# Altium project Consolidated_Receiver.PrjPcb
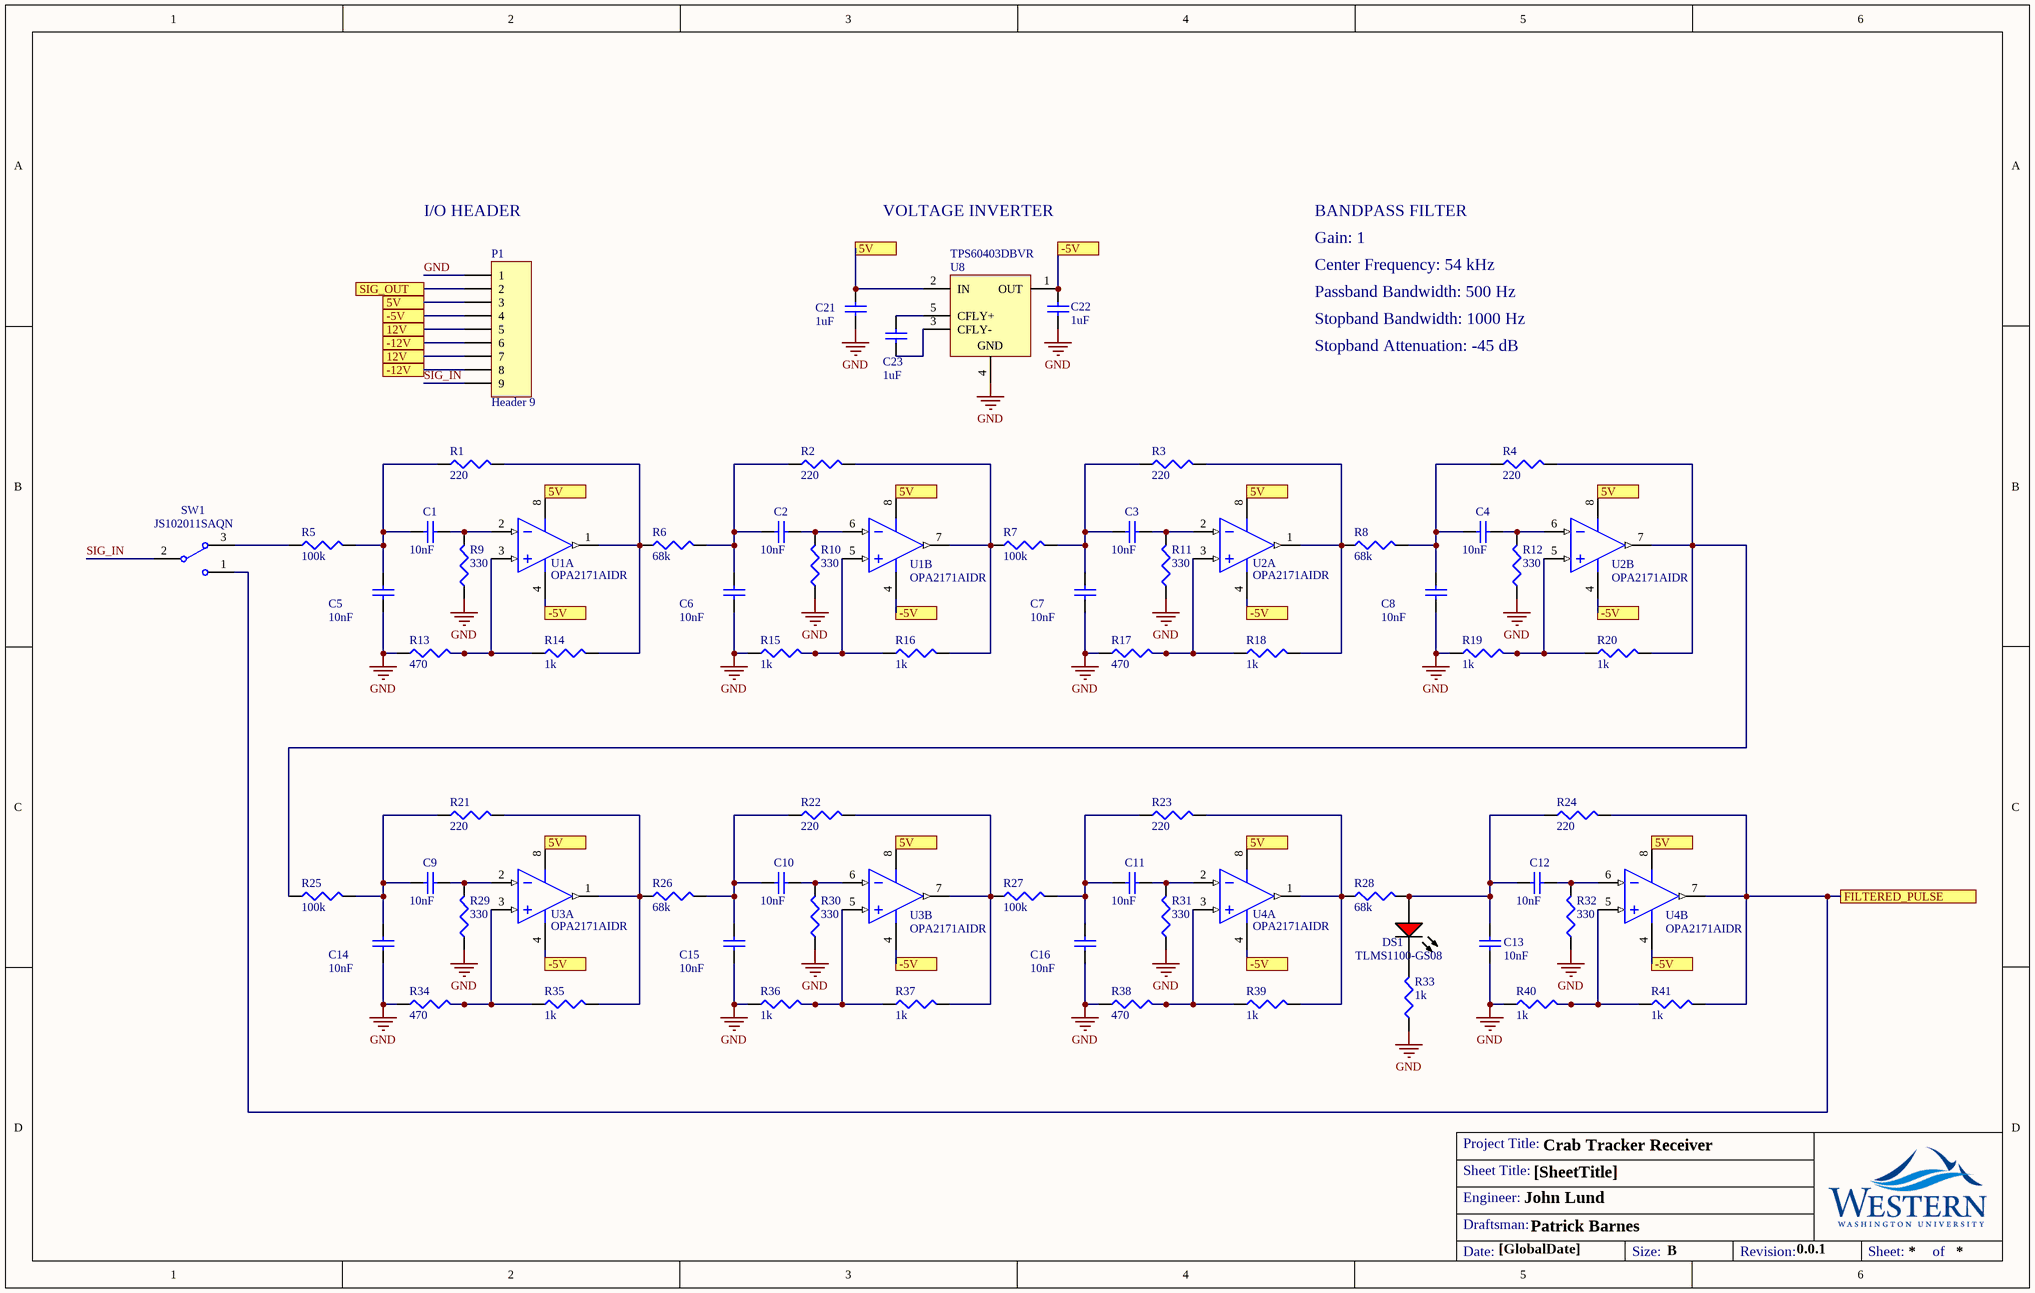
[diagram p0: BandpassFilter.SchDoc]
DraftsmanName: Patrick Barnes; EngineerName: John Lund; GlobalDate: [GlobalDate]; GlobalTitle: Crab Tracker Receiver; RevNumber: 0.0.1
3 sheets, 87 parts. Net scope: flat (ports and power ports of the same name join across sheets).
Board files: 2LayerPCBTemplateWWU.PcbDoc, PCB1.PcbDoc
Sheets:
  BandpassFilter.SchDoc
  ADC.SchDoc
  SchmittTrigger.SchDoc

## Sheet BandpassFilter.SchDoc: [SheetTitle]
size B; Date: [Date]

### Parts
C1  10nF  [1608[0603]]
C2  10nF  [1608[0603]]
C3  10nF  [1608[0603]]
C4  10nF  [1608[0603]]
C5  10nF  [1608[0603]]
C6  10nF  [1608[0603]]
C7  10nF  [1608[0603]]
C8  10nF  [1608[0603]]
C9  10nF  [1608[0603]]
C10  10nF  [1608[0603]]
C11  10nF  [1608[0603]]
C12  10nF  [1608[0603]]
C13  10nF  [1608[0603]]
C14  10nF  [1608[0603]]
C15  10nF  [1608[0603]]
C16  10nF  [1608[0603]]
C21  1uF  [1608[0603]]
C22  1uF  [1608[0603]]
C23  1uF  [1608[0603]]
DS1  TLMS1100-GS08  [VISH-TLMX1100_V]
P1  Header 9  [HDR1X9]
R1  220  [J1-0603]
R2  220  [J1-0603]
R3  220  [J1-0603]
R4  220  [J1-0603]
R5  100k  [J1-0603]
R6  68k  [J1-0603]
R7  100k  [J1-0603]
R8  68k  [J1-0603]
R9  330  [J1-0603]
R10  330  [J1-0603]
R11  330  [J1-0603]
R12  330  [J1-0603]
R13  470  [J1-0603]
R14  1k  [J1-0603]
R15  1k  [J1-0603]
R16  1k  [J1-0603]
R17  470  [J1-0603]
R18  1k  [J1-0603]
R19  1k  [J1-0603]
R20  1k  [J1-0603]
R21  220  [J1-0603]
R22  220  [J1-0603]
R23  220  [J1-0603]
R24  220  [J1-0603]
R25  100k  [J1-0603]
R26  68k  [J1-0603]
R27  100k  [J1-0603]
R28  68k  [J1-0603]
R29  330  [J1-0603]
R30  330  [J1-0603]
R31  330  [J1-0603]
R32  330  [J1-0603]
R33  1k  [J1-0603]
R34  470  [J1-0603]
R35  1k  [J1-0603]
R36  1k  [J1-0603]
R37  1k  [J1-0603]
R38  470  [J1-0603]
R39  1k  [J1-0603]
R40  1k  [J1-0603]
R41  1k  [J1-0603]
SW1  JS102011SAQN  [CKCP-JS102011SAQN-3_V]
U1  OPA2171AIDR  [D0008A_N]  (parts A,B of 2)
U2  OPA2171AIDR  [D0008A_N]  (parts A,B of 2)
U3  OPA2171AIDR  [D0008A_N]  (parts A,B of 2)
U4  OPA2171AIDR  [D0008A_N]  (parts A,B of 2)
U8  TPS60403DBVR  [DBV0005A_M]

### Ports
5V, 12V, -5V, -12V, FILTERED_PULSE, SIG_OUT

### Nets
GND: C5.1 C6.1 C7.1 C8.1 C13.1 C14.1 C15.1 C16.1 C21.1 C22.1 P1.1 R9.1 R10.1 R11.1 R12.1 R13.1 R15.1 R17.1 R19.1 R29.1 R30.1 R31.1 R32.1 R33.1 R34.1 R36.1 R38.1 R40.1 U8.4(GND)
SIG_IN: P1.9 SW1.2
NetC1_1: C1.1 C5.2 R1.1 R5.2
NetC1_2: C1.2 R9.2 U1.2(IN_A-)
NetC2_1: C2.1 C6.2 R2.1 R6.2
NetC2_2: C2.2 R10.2 U1.6(IN_B-)
NetC3_1: C3.1 C7.2 R3.1 R7.2
NetC3_2: C3.2 R11.2 U2.2(IN_A-)
NetC4_1: C4.1 C8.2 R4.1 R8.2
NetC4_2: C4.2 R12.2 U2.6(IN_B-)
NetC9_1: C9.1 C14.2 R21.1 R25.2
NetC9_2: C9.2 R29.2 U3.2(IN_A-)
NetC10_1: C10.1 C15.2 R22.1 R26.2
NetC10_2: C10.2 R30.2 U3.6(IN_B-)
NetC11_1: C11.1 C16.2 R23.1 R27.2
NetC11_2: C11.2 R31.2 U4.2(IN_A-)
NetC12_1: C12.1 C13.2 DS1.1(A) R24.1 R28.2
NetC12_2: C12.2 R32.2 U4.6(IN_B-)
NetC21_2: C21.2 P1.3 U1.8(V+) U2.8(V+) U3.8(V+) U4.8(V+) U8.2(IN) ; port 5V
NetC22_2: C22.2 P1.4 U1.4(V-) U2.4(V-) U3.4(V-) U4.4(V-) U8.1(OUT) ; port -5V
NetC23_1: C23.1 U8.5(CFLY+)
NetC23_2: C23.2 U8.3(CFLY-)
NetDS1_2: DS1.2(K) R33.2
NetP1_2: P1.2 ; port SIG_OUT
NetP1_5: P1.5 P1.7 ; port 12V
NetP1_6: P1.6 P1.8 ; port -12V
NetR1_2: R1.2 R6.1 R14.2 U1.1(OUT_A)
NetR2_2: R2.2 R7.1 R16.2 U1.7(OUT_B)
NetR3_2: R3.2 R8.1 R18.2 U2.1(OUT_A)
NetR4_2: R4.2 R20.2 R25.1 U2.7(OUT_B)
NetR5_1: R5.1 SW1.3
NetR13_2: R13.2 R14.1 U1.3(IN_A+)
NetR15_2: R15.2 R16.1 U1.5(IN_B+)
NetR17_2: R17.2 R18.1 U2.3(IN_A+)
NetR19_2: R19.2 R20.1 U2.5(IN_B+)
NetR21_2: R21.2 R26.1 R35.2 U3.1(OUT_A)
NetR22_2: R22.2 R27.1 R37.2 U3.7(OUT_B)
NetR23_2: R23.2 R28.1 R39.2 U4.1(OUT_A)
NetR24_2: R24.2 R41.2 SW1.1 U4.7(OUT_B) ; port FILTERED_PULSE
NetR34_2: R34.2 R35.1 U3.3(IN_A+)
NetR36_2: R36.2 R37.1 U3.5(IN_B+)
NetR38_2: R38.2 R39.1 U4.3(IN_A+)
NetR40_2: R40.2 R41.1 U4.5(IN_B+)

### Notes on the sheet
- I/O HEADER
- VOLTAGE INVERTER
- BANDPASS FILTER
- Gain: 1
- Center Frequency: 54 kHz
- Passband Bandwidth: 500 Hz
- Stopband Bandwidth: 1000 Hz
- Stopband Attenuation: -45 dB

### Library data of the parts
C1-C16 C21-C23 = Cap Semi: Capacitor (Semiconductor SIM Model)
DS1 = CMP-1666-00027-1: LED, RED, 2.1 V, -40 to 100 degC, 2-Pin SMD (0603), RoHS, Tape and Reel; Type (Capacitors): C0G; Resistance: 100000000000 Ohm; Capacitance: 12 pF; Voltage Rating: 50 V; Tolerance: 5%
P1 = Header 9: Header, 9-Pin
R1-R41 = Res3: Resistor
SW1 = CMP-2000-06501-1: Sub-Miniature Slide Switch, SPDT, -40 to 85 degC, 3-Pin SMD, RoHS, Tape and Reel; Manufacturer: C&K Components; Electrical Life: 15000Cycles; Actuator Color: Black; Body Orientation: RightAngle; Minimum Insulation Resistance: 100MOhm; Contact Rating @ Voltage: 0.3@6VDCA; Actuator Style: SideSlide; Maximum DC Voltage Rating: 6V; COO: US; Actuator Material: Nylon4/6; Dielectric Strength: 500VAC; Maximum Contact Resistance: 70mOhm
U1-U4 = CMP-0272-00237-3: Low Power, RRO, General Purpose Operational Amplifier in MicroPackage, 2.7 to 36 V, -40 to 125 degC, 8-pin SOIC (D8), Green (RoHS & no Sb/Br); Manufacturer: Texas Instruments; Packing: LARGE T&R; Sub Family: High Supply Voltage Amplifier (>=30V), Low Supply Voltage Amplifier (<=2.7V), Precision Amplifier; Number of Channels: 2; CMRR(Min)(dB): 104; Rating: Catalog; Total Supply Voltage(Max)(+5V is 5, +/-5V is 10): 36; Iq per channel(Max)(mA): 0.595; Slew Rate(Typ)(V/us): 1.5; GBW(Typ)(MHz): 3; Vio (25C)(Max)(mV): 1.8; IIB(Max)(pA): 15; Total Supply Voltage(Min)(+5V is 5, +/-5V is 10): 2.7; Offset Drift(Typ)(uV/C): 0.3
U8 = CMP-0391-00006-2: -1.8 to -5.25 V, Inverting Charge Pump Regulator, 60 mA, 1.8 to 5.25 V Input with 2-Cell Alkaline / Nixx Input, -40 to 85 degC, 5-pin SOT23 (DBV5), Green (RoHS & no Sb/Br); Manufacturer: Texas Instruments; Iout(Max)(A): 0.06; Topology: Inverting Buck/Boost; Vin(Max)(V): 5.25; Iq(Typ)(mA): 0.425; Vin(Min)(V): 1.8; Switching Frequency(Max)(kHz): 300; 2-Cell Alkaline/Nixx Input: TRUE; Efficiency(Typ)(%): 99

## Sheet ADC.SchDoc: [SheetTitle]
size B; Date: [Date]
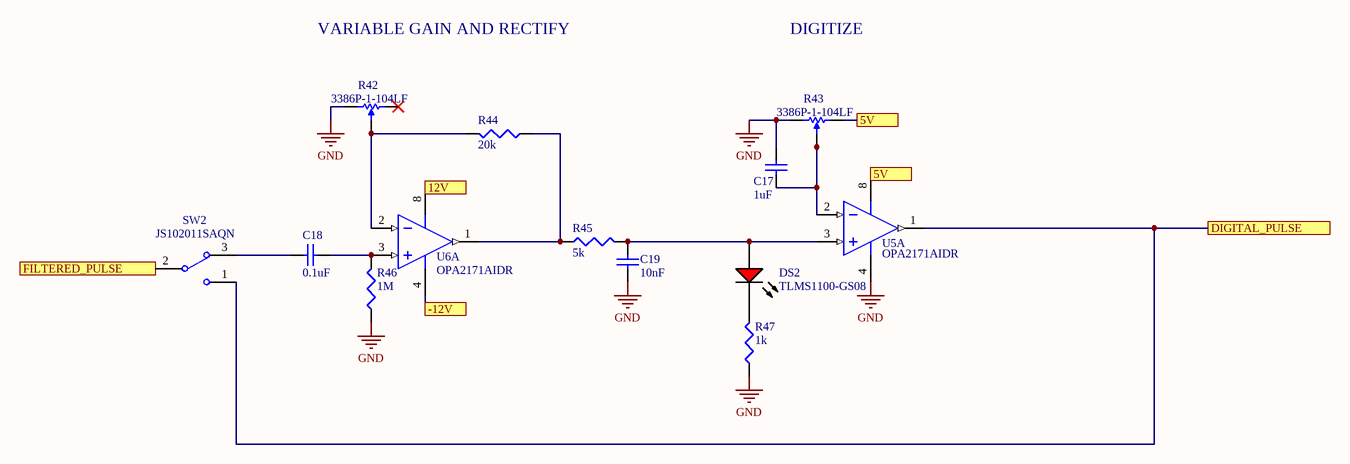
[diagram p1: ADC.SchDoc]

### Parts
C17  1uF  [1608[0603]]
C18  0.1uF  [1608[0603]]
C19  10nF  [1608[0603]]
DS2  TLMS1100-GS08  [VISH-TLMX1100_V]
R42  3386P-1-104LF  [BOUR-3386P]
R43  3386P-1-104LF  [BOUR-3386P]
R44  20k  [J1-0603]
R45  5k  [J1-0603]
R46  1M  [J1-0603]
R47  1k  [J1-0603]
SW2  JS102011SAQN  [CKCP-JS102011SAQN-3_V]
U5  OPA2171AIDR  [D0008A_N]  (part A of 2)
U6  OPA2171AIDR  [D0008A_N]  (part A of 2)

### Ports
5V, 12V, -12V, DIGITAL_PULSE, FILTERED_PULSE

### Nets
GND: C17.2 C19.1 R42.1 R43.1 R46.1 R47.1 U5.4(V-)
NetC17_1: C17.1 R43.2 U5.2(IN_A-)
NetC18_1: C18.1 SW2.3
NetC18_2: C18.2 R46.2 U6.3(IN_A+)
NetC19_2: C19.2 DS2.1(A) R45.2 U5.3(IN_A+)
NetC21_2: R43.3 U5.8(V+) ; port 5V
NetDS2_2: DS2.2(K) R47.2
NetP1_5: U6.8(V+) ; port 12V
NetP1_6: U6.4(V-) ; port -12V
NetR24_2: SW2.2 ; port FILTERED_PULSE
NetR42_2: R42.2 R44.2 U6.2(IN_A-)
NetR44_1: R44.1 R45.1 U6.1(OUT_A)
NetSW2_1: SW2.1 U5.1(OUT_A) ; port DIGITAL_PULSE

Not connected (* = marked no-connect by the designer): R42 3*

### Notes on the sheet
- VARIABLE GAIN AND RECTIFY
- DIGITIZE

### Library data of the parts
C17-C19 = Cap Semi: Capacitor (Semiconductor SIM Model)
DS2 = CMP-1666-00027-1: as DS1 on sheet BandpassFilter
R42 R43 = CMP-2000-05592-1: Square Trimpot(R) Trimming Potentiometer, 100 KOhm, +/- 10%, 0.5 W, -55 to 125 degC, 3-Pin THD, RoHS, Tube; Manufacturer Series: 3386; Manufacturer: Bourns; Resistive Element Material: Cermet; Shaft Diameter: 3.15mm; Number of Turns: 1; Product Height: 4.83mm; Temperature Coefficient: 100ppm/C; Product Depth: 9.53mm; Rated Temperature (Cel): 85; Actuator Orientation: Vertical; Resistance (ohm): 100000; Power Rating: 1/2W; Tolerance (%): 10; Rated Power Dissipation (P) (W): 0.5; Resistance Law: Linear; Actuator Type: Screw
R44-R47 = Res3: Resistor
SW2 = CMP-2000-06501-1: as SW1 on sheet BandpassFilter
U5 U6 = CMP-0272-00237-3: as U1 on sheet BandpassFilter

## Sheet SchmittTrigger.SchDoc: [SheetTitle]
size B; Date: [Date]
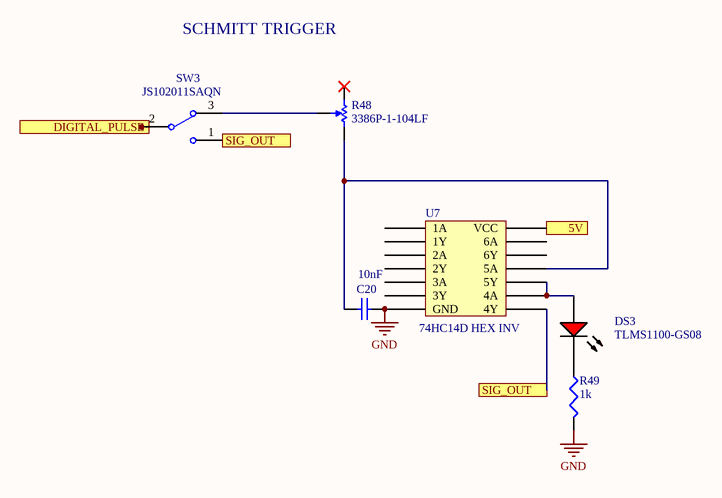
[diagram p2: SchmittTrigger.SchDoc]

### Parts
C20  10nF  [1608[0603]]
DS3  TLMS1100-GS08  [VISH-TLMX1100_V]
R48  3386P-1-104LF  [BOUR-3386P]
R49  1k  [J1-0603]
SW3  JS102011SAQN  [CKCP-JS102011SAQN-3_V]
U7  74HC14D HEX INV  [14-SOIC]

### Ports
5V, DIGITAL_PULSE, SIG_OUT

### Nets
GND: C20.2 R49.2 U7.7(GND)
NetC20_1: C20.1 R48.3 U7.11(5A)
NetC21_2: U7.14(VCC) ; port 5V
NetDS3_1: DS3.1(A) U7.9(4A) U7.10(5Y)
NetDS3_2: DS3.2(K) R49.1
NetP1_2: SW3.1 U7.8(4Y) ; port SIG_OUT
NetR48_2: R48.2 SW3.3

Not connected (* = marked no-connect by the designer): R48 1*; SW3 2; U7 1(1A) 2(1Y) 3(2A) 4(2Y) 5(3A) 6(3Y) 12(6Y) 13(6A)

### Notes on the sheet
- SCHMITT TRIGGER

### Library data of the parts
C20 = Cap Semi: Capacitor (Semiconductor SIM Model)
DS3 = CMP-1666-00027-1: as DS1 on sheet BandpassFilter
R48 = CMP-2000-05592-1: as R42 on sheet ADC
R49 = Res3: Resistor
SW3 = CMP-2000-06501-1: as SW1 on sheet BandpassFilter
U7 = SCHMITT INVERTER 6INV 74HC14: 74HC14D Schmitt triggered inverter

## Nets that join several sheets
GND: BandpassFilter (29 pins), ADC (7 pins), SchmittTrigger (C20.2 R49.2 U7.7)
NetC21_2: BandpassFilter (7 pins), ADC (R43.3 U5.8), SchmittTrigger (U7.14)
NetP1_2: BandpassFilter (P1.2), SchmittTrigger (SW3.1 U7.8)
NetP1_5: BandpassFilter (P1.5 P1.7), ADC (U6.8)
NetP1_6: BandpassFilter (P1.6 P1.8), ADC (U6.4)
NetR24_2: BandpassFilter (R24.2 R41.2 SW1.1 U4.7), ADC (SW2.2)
